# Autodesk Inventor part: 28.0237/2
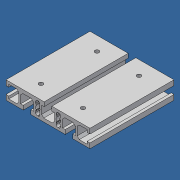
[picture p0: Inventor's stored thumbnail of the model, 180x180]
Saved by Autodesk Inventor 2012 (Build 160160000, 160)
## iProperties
Created: 2007-06
Part Number: 28.0237/2
Material: Aluminum-6061
Document SubType Name: Modeling
Designer: Andy Moles
Density: 2.71 g/cm^3
Description: L = 3.543", MACHINE TO 28.0237/2
Mass: 175.7 g
Surface Area: 445.063 cm^2
Volume: 64.8339 cm^3
Stock Number: 20.0995 PROFILE 90X19
Vendor: F
Author: Andy Moles
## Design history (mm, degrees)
sketch "Sketch1"
  geometry: L1 (18.4, -9.5)-(18.4, -5) reference; L2 (17.9, -5)-(15.7, -5) reference; L3 (15.7, -5)-(15.7, 3.5) reference; L4 (15.7, 3.5)-(18, 5.8) reference; L5 (18, 5.8)-(27, 5.8) reference; L6 (27, 5.8)-(29.3, 3.5) reference; L7 (29.3, 3.5)-(29.3, -5) reference; L8 (26.6, -5)-(26.6, -9.5) reference; L9 (45, -9.5)-(26.9, -9.5) reference; L10 (45, -4.1)-(45, -9.5) reference; L11 (45, -4.1)-(42, -4.1) reference; L12 (42, -4.6)-(42, -6.8) reference; L13 (42, -6.8)-(33.5, -6.8) reference; L14 (33.5, -6.8)-(31.2, -4.5) reference; L15 (31.2, -4.5)-(31.2, 4.5) reference; L16 (31.2, 4.5)-(33.5, 6.8) reference; L17 (33.5, 6.8)-(42, 6.8) reference; L18 (42, 4.1)-(45, 4.1) reference; L19 (45, 9.5)-(45, 4.1) reference; L20 (4.4, 9.5)-(45, 9.5) reference; L21 (4.1, 9.5)-(4.1, 5) reference; L22 (4.6, 5)-(6.8, 5) reference; L23 (6.8, 5)-(6.8, -3.5) reference; L24 (6.8, -3.5)-(4.5, -5.8) reference; L25 (4.5, -5.8)-(-4.5, -5.8) reference; L26 (-4.5, -5.8)-(-6.8, -3.5) reference; L27 (-6.8, -3.5)-(-6.8, 5) reference; L28 (-4.1, 5)-(-4.1, 9.5) reference; L29 (-45, 4.1)-(-45, 9.5) reference; L30 (-45, 4.1)-(-42, 4.1) reference; L31 (-42, 4.1)-(-42, 6.8) reference; L32 (-42, 6.8)-(-33.5, 6.8) reference; L33 (-33.5, 6.8)-(-31.2, 4.5) reference; L34 (-31.2, 4.5)-(-31.2, -4.5) reference; L35 (-31.2, -4.5)-(-33.5, -6.8) reference; L36 (-33.5, -6.8)-(-42, -6.8) reference; L37 (-42, -6.8)-(-42, -4.1) reference; L38 (-42, -4.1)-(-45, -4.1) reference; L39 (-45, -9.5)-(-45, -4.1) reference; L40 (-26.6, -9.5)-(-26.6, -5) reference; L41 (-29.3, -5)-(-29.3, 3.5) reference; L42 (-29.3, 3.5)-(-27, 5.8) reference; L43 (-27, 5.8)-(-18, 5.8) reference; L44 (-18, 5.8)-(-15.7, 3.5) reference; L45 (-15.7, 3.5)-(-15.7, -5) reference; L46 (-15.7, -5)-(-17.9, -5) reference; L47 (-18.4, -5)-(-18.4, -9.5) reference; L48 (-18.1, -9.5)-(-18.4, -9.5) reference; L49 (-26.6, -9.5)-(-45, -9.5) reference; L50 (-17.9, -5)-(-18.4, -5) reference; L51 (-26.6, -5)-(-29.3, -5) reference; L52 (-6.8, 5)-(-4.1, 5) reference; L53 (4.1, 5)-(4.6, 5) reference; L54 (-45, 9.5)-(-4.1, 9.5) reference; L55 (4.1, 9.5)-(4.4, 9.5) reference; L56 (29.3, -5)-(26.6, -5) reference; L57 (18.4, -5)-(17.9, -5) reference; L58 (26.9, -9.5)-(26.6, -9.5) reference; L59 (18.4, -9.5)-(-18.1, -9.5) reference; L60 (42, 6.8)-(42, 4.1) reference; L61 (42, -4.1)-(42, -4.6) reference; L62 (-9.354, -2.59)-(-8.993, -2.95); L63 (-10.7, -7)-(-11.3, -7); L64 (-8.7, -3.657)-(-8.7, -5)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; A1 r 2.5 centre (-11, 0) between (-9.333, -1.863) and (-9.333, 1.863); A2 r 1 centre (-9.7, -3.657) between (-8.7, -3.657) and (-8.993, -2.95); A3 r 2 centre (-10.7, -5) between (-10.7, -7) and (-8.7, -5); A4 r 0.5 centre (-9, -2.236) between (-9.333, -1.863) and (-9.354, -2.59); A5 r 1 centre (-12.3, -3.657) between (-13.007, -2.95) and (-13.3, -3.657); A6 r 2.5 centre (-11, 0) between (-12.667, 1.863) and (-12.667, -1.863); A7 r 2 centre (-11.3, -5) between (-13.3, -5) and (-11.3, -7); A8 r 0.5 centre (-13, -2.236) between (-12.646, -2.59) and (-12.667, -1.863); A9 r 0.5 centre (-13, 2.236) between (-12.667, 1.863) and (-12.646, 2.59); A10 r 2 centre (-11.3, 5) between (-11.3, 7) and (-13.3, 5); A11 r 0.5 centre (-9, 2.236) between (-9.354, 2.59) and (-9.333, 1.863); A12 r 1 centre (-9.7, 3.657) between (-8.993, 2.95) and (-8.7, 3.657); A13 r 2 centre (-10.7, 5) between (-8.7, 5) and (-10.7, 7); A14 r 1 centre (-12.3, 3.657) between (-13.3, 3.657) and (-13.007, 2.95); A15 r 1 centre (12.3, 3.657) between (13.007, 2.95) and (13.3, 3.657); A16 r 0.5 centre (13, 2.236) between (12.646, 2.59) and (12.667, 1.863); A17 r 2 centre (11.3, 5) between (13.3, 5) and (11.3, 7); A18 r 0.5 centre (9, 2.236) between (9.333, 1.863) and (9.354, 2.59); A19 r 1 centre (9.7, 3.657) between (8.7, 3.657) and (8.993, 2.95); A20 r 2 centre (10.7, 5) between (10.7, 7) and (8.7, 5); A21 r 1 centre (9.7, -3.657) between (8.993, -2.95) and (8.7, -3.657); A22 r 2.5 centre (11, 0) between (9.333, 1.863) and (9.333, -1.863); A23 r 0.5 centre (9, -2.236) between (9.354, -2.59) and (9.333, -1.863); A24 r 2 centre (10.7, -5) between (8.7, -5) and (10.7, -7); A25 r 2.5 centre (11, 0) between (12.667, -1.863) and (12.667, 1.863); A26 r 0.5 centre (13, -2.236) between (12.667, -1.863) and (12.646, -2.59); A27 r 1 centre (12.3, -3.657) between (13.3, -3.657) and (13.007, -2.95); A28 r 2 centre (11.3, -5) between (11.3, -7) and (13.3, -5)
  constraints: 162 end point, 56 point on circle, 28 centre point, 28 horizontal, 23 vertical, 71 other
extrude "Extrusion1" new body sketch "Sketch1" stored distance "d0" = 90; taper "d1" = 0 deg
sketch "Sketch2"
  geometry: L1 (-26.6, -90)-(-26.6, 0) reference; L2 (63.4, -90)-(63.4, 0) reference; L3 (-8.2, 0)-(-26.6, 0) reference; L4 (-26.6, -90)-(-8.2, -90) reference; 5 further points
  constraints: 2 horizontal alignment, 2 vertical alignment
  dimensions: "d2" = 22.5 distance from line of point (-4.1, -15) L1; "d3" = 22.5 distance from line of point (40.9, -15) L2; "d4" = 15 distance from line of point (-4.1, -15) L3; "d5" = 15 distance from line of point (-4.1, -75) L4
hole "Hole1" sketch "Sketch2" at (40.9, -15), (40.9, -75), (-4.1, -75), (-4.1, -15) diameter "d6" = 4.5; stored, may be unused: countersink angle "d10" = 90 deg, drill point angle "d12" = 118 deg; dims "d7" = 6, "d8" = 4, "d9" = 2, "d11" = 4.5
sketch "Sketch3"
  geometry: 3 further points
  constraints: 2 vertical alignment
  dimensions: "d13" = 22.5 distance of point (18.4, -67.5) point (18.4, -45); "d14" = 22.5 distance of point (18.4, -22.5) point (18.4, -45)
hole "Hole2" sketch "Sketch3" at (18.4, -67.5), (18.4, -22.5) diameter "d15" = 5.5; stored, may be unused: countersink angle "d19" = 90 deg, drill point angle "d21" = 118 deg; dims "d16" = 6, "d17" = 11.5, "d18" = 2, "d20" = 8
body "Solid1"
